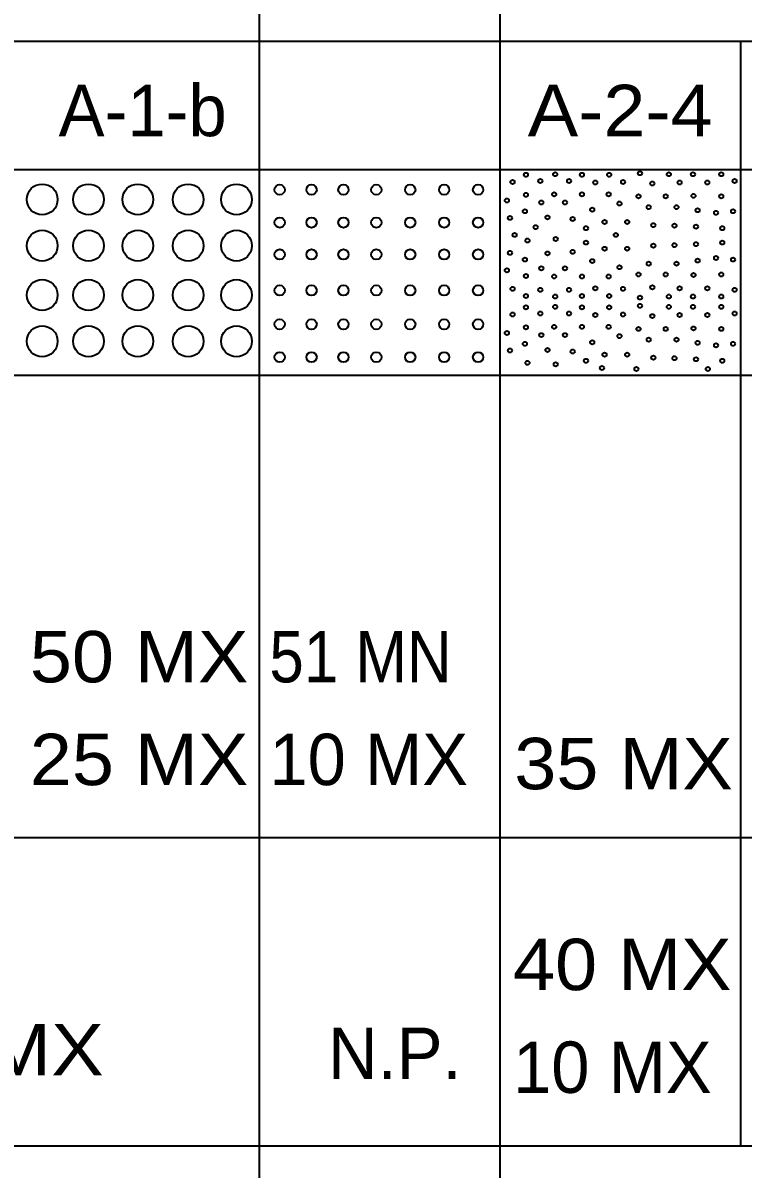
# Model space of a CAD drawing. Extents: x 2137492.6 to 2137529.1, y 2137475.8 to 2137563.
# Drawn here: x 2137494.599 to 2137496, y 2137553.178 to 2137555.408 of the extents above; entities that cross this region are included whole.
import ezdxf
from ezdxf.enums import TextEntityAlignment as Align

# ---------------------------------------------------------------- set-up
doc = ezdxf.new("R2010")
doc.units = 0
doc.header["$LTSCALE"] = 0.04
doc.layers.add('1', color=7, linetype='Continuous', lineweight=35)

msp = doc.modelspace()

# ---------------------------------------------------------------- linework, layer by layer
at = {"layer": '1'}
for p, q in [((2137495.059, 2137552.223), (2137495.059, 2137555.621)), ((2137495.527, 2137552.223), (2137495.527, 2137555.621)), ((2137494.121, 2137555.373), (2137499.271, 2137555.373)), ((2137495.995, 2137553.223), (2137495.995, 2137555.374)), ((2137493.171, 2137555.123), (2137501.871, 2137555.123)), ((2137493.171, 2137554.723), (2137501.871, 2137554.723)), ((2137493.171, 2137553.823), (2137501.871, 2137553.823)), ((2137493.171, 2137553.223), (2137499.271, 2137553.223))]:
    msp.add_line(p, q, dxfattribs=at)
for centre, radius in [((2137495.57706, 2137555.11286), 0.004), ((2137495.63406, 2137555.11386), 0.004), ((2137495.68606, 2137555.11286), 0.004), ((2137495.73906, 2137555.11286), 0.004), ((2137495.79906, 2137555.11586), 0.004), ((2137495.85506, 2137555.11386), 0.004), ((2137495.90206, 2137555.11386), 0.004), ((2137495.95706, 2137555.11386), 0.004), ((2137494.63606, 2137555.06486), 0.03), ((2137494.72606, 2137555.06486), 0.03), ((2137494.82206, 2137555.06486), 0.03), ((2137494.92006, 2137555.06486), 0.03), ((2137495.01406, 2137555.06486), 0.03), ((2137495.09806, 2137555.08386), 0.01), ((2137495.16006, 2137555.08386), 0.01), ((2137495.22206, 2137555.08386), 0.01), ((2137495.28606, 2137555.08386), 0.01), ((2137495.35206, 2137555.08386), 0.01), ((2137495.41806, 2137555.08386), 0.01), ((2137495.48406, 2137555.08386), 0.01), ((2137495.55106, 2137555.09886), 0.004), ((2137495.60506, 2137555.10086), 0.004), ((2137495.66106, 2137555.10086), 0.004), ((2137495.71206, 2137555.09786), 0.004), ((2137495.76606, 2137555.09886), 0.004), ((2137495.82306, 2137555.09586), 0.004), ((2137495.87606, 2137555.09786), 0.004), ((2137495.93006, 2137555.09786), 0.004), ((2137495.98306, 2137555.10086), 0.004), ((2137495.57706, 2137555.07386), 0.004), ((2137495.63206, 2137555.07486), 0.004), ((2137495.68606, 2137555.07486), 0.004), ((2137495.73806, 2137555.07486), 0.004), ((2137495.79606, 2137555.07086), 0.004), ((2137495.84906, 2137555.07086), 0.004), ((2137495.90306, 2137555.07186), 0.004), ((2137495.95706, 2137555.07086), 0.004), ((2137495.54006, 2137555.06286), 0.004), ((2137495.60706, 2137555.05886), 0.004), ((2137495.65306, 2137555.05886), 0.004), ((2137495.70606, 2137555.04486), 0.004), ((2137495.75906, 2137555.05686), 0.004), ((2137495.81606, 2137555.04986), 0.004), ((2137495.87006, 2137555.04986), 0.004), ((2137495.91106, 2137555.04386), 0.004), ((2137495.09806, 2137555.01986), 0.01), ((2137495.16006, 2137555.01986), 0.01), ((2137495.22206, 2137555.01986), 0.01), ((2137495.28606, 2137555.01986), 0.01), ((2137495.35206, 2137555.01986), 0.01), ((2137495.41806, 2137555.01986), 0.01), ((2137495.48406, 2137555.01986), 0.01), ((2137495.54606, 2137555.02886), 0.004), ((2137495.57506, 2137555.04186), 0.004), ((2137495.61906, 2137555.02986), 0.004), ((2137495.66806, 2137555.02686), 0.004), ((2137495.94706, 2137555.03886), 0.004), ((2137495.98006, 2137555.04186), 0.004), ((2137494.63606, 2137554.97486), 0.03), ((2137494.72606, 2137554.97486), 0.03), ((2137494.82206, 2137554.97486), 0.03), ((2137494.92006, 2137554.97486), 0.03), ((2137495.01406, 2137554.97486), 0.03), ((2137495.59606, 2137555.01086), 0.004), ((2137495.69406, 2137555.00886), 0.004), ((2137495.73006, 2137555.02086), 0.004), ((2137495.77406, 2137555.02086), 0.004), ((2137495.82506, 2137555.01486), 0.004), ((2137495.86606, 2137555.01386), 0.004), ((2137495.90806, 2137555.01186), 0.004), ((2137495.95906, 2137555.00886), 0.004), ((2137495.55506, 2137554.99586), 0.004), ((2137495.58006, 2137554.98486), 0.004), ((2137495.63506, 2137554.98786), 0.004), ((2137495.69406, 2137554.98086), 0.004), ((2137495.75206, 2137554.99586), 0.004), ((2137495.90806, 2137554.97786), 0.004), ((2137495.95906, 2137554.98086), 0.004), ((2137495.09806, 2137554.95786), 0.01), ((2137495.16006, 2137554.95786), 0.01), ((2137495.22206, 2137554.95786), 0.01), ((2137495.28606, 2137554.95786), 0.01), ((2137495.35206, 2137554.95786), 0.01), ((2137495.41806, 2137554.95786), 0.01), ((2137495.48406, 2137554.95786), 0.01), ((2137495.54606, 2137554.96086), 0.004), ((2137495.61906, 2137554.95986), 0.004), ((2137495.66806, 2137554.96286), 0.004), ((2137495.73006, 2137554.96886), 0.004), ((2137495.77406, 2137554.96886), 0.004), ((2137495.82506, 2137554.97486), 0.004), ((2137495.86606, 2137554.97586), 0.004), ((2137495.57506, 2137554.94786), 0.004), ((2137495.70606, 2137554.94486), 0.004), ((2137495.75906, 2137554.93286), 0.004), ((2137495.81606, 2137554.93986), 0.004), ((2137495.87006, 2137554.93986), 0.004), ((2137495.91106, 2137554.94586), 0.004), ((2137495.94706, 2137554.95086), 0.004), ((2137495.98006, 2137554.94786), 0.004), ((2137495.54006, 2137554.92686), 0.004), ((2137495.57706, 2137554.91586), 0.004), ((2137495.60706, 2137554.93086), 0.004), ((2137495.63206, 2137554.91486), 0.004), ((2137495.65306, 2137554.93086), 0.004), ((2137495.68606, 2137554.91486), 0.004), ((2137495.73806, 2137554.91486), 0.004), ((2137495.79606, 2137554.91886), 0.004), ((2137495.84906, 2137554.91886), 0.004), ((2137495.90306, 2137554.91786), 0.004), ((2137495.95706, 2137554.91886), 0.004), ((2137494.63606, 2137554.87886), 0.03), ((2137494.72606, 2137554.87886), 0.03), ((2137494.82206, 2137554.87886), 0.03), ((2137494.92006, 2137554.87886), 0.03), ((2137495.01406, 2137554.87886), 0.03), ((2137495.09806, 2137554.88786), 0.01), ((2137495.16006, 2137554.88786), 0.01), ((2137495.22206, 2137554.88786), 0.01), ((2137495.28606, 2137554.88786), 0.01), ((2137495.35206, 2137554.88786), 0.01), ((2137495.41806, 2137554.88786), 0.01), ((2137495.48406, 2137554.88786), 0.01), ((2137495.55106, 2137554.89086), 0.004), ((2137495.60506, 2137554.88886), 0.004), ((2137495.66106, 2137554.88886), 0.004), ((2137495.71206, 2137554.89186), 0.004), ((2137495.76606, 2137554.89086), 0.004), ((2137495.82306, 2137554.89386), 0.004), ((2137495.87606, 2137554.89186), 0.004), ((2137495.93006, 2137554.89186), 0.004), ((2137495.98306, 2137554.88886), 0.004), ((2137495.57706, 2137554.87686), 0.004), ((2137495.63406, 2137554.87586), 0.004), ((2137495.68606, 2137554.87686), 0.004), ((2137495.73906, 2137554.87686), 0.004), ((2137495.79906, 2137554.87386), 0.004), ((2137495.85506, 2137554.87586), 0.004), ((2137495.90206, 2137554.87586), 0.004), ((2137495.95706, 2137554.87586), 0.004), ((2137495.57706, 2137554.85486), 0.004), ((2137495.60506, 2137554.84286), 0.004), ((2137495.63406, 2137554.85586), 0.004), ((2137495.66106, 2137554.84286), 0.004), ((2137495.68606, 2137554.85486), 0.004), ((2137495.73906, 2137554.85486), 0.004), ((2137495.79906, 2137554.85786), 0.004), ((2137495.85506, 2137554.85586), 0.004), ((2137495.90206, 2137554.85586), 0.004), ((2137495.95706, 2137554.85586), 0.004), ((2137495.98306, 2137554.84286), 0.004), ((2137495.09806, 2137554.82186), 0.01), ((2137495.16006, 2137554.82186), 0.01), ((2137495.22206, 2137554.82186), 0.01), ((2137495.28606, 2137554.82186), 0.01), ((2137495.35206, 2137554.82186), 0.01), ((2137495.41806, 2137554.82186), 0.01), ((2137495.48406, 2137554.82186), 0.01), ((2137495.55106, 2137554.84086), 0.004), ((2137495.71206, 2137554.83986), 0.004), ((2137495.76606, 2137554.84086), 0.004), ((2137495.82306, 2137554.83786), 0.004), ((2137495.87606, 2137554.83986), 0.004), ((2137495.93006, 2137554.83986), 0.004), ((2137494.63606, 2137554.78886), 0.03), ((2137494.72606, 2137554.78886), 0.03), ((2137494.82206, 2137554.78886), 0.03), ((2137494.92006, 2137554.78886), 0.03), ((2137495.01406, 2137554.78886), 0.03), ((2137495.54006, 2137554.80486), 0.004), ((2137495.57706, 2137554.81586), 0.004), ((2137495.60706, 2137554.80086), 0.004), ((2137495.63206, 2137554.81686), 0.004), ((2137495.65306, 2137554.80086), 0.004), ((2137495.68606, 2137554.81686), 0.004), ((2137495.73806, 2137554.81686), 0.004), ((2137495.75906, 2137554.79886), 0.004), ((2137495.79606, 2137554.81286), 0.004), ((2137495.84906, 2137554.81286), 0.004), ((2137495.90306, 2137554.81386), 0.004), ((2137495.95706, 2137554.81286), 0.004), ((2137495.57506, 2137554.78386), 0.004), ((2137495.70606, 2137554.78686), 0.004), ((2137495.81606, 2137554.79186), 0.004), ((2137495.87006, 2137554.79186), 0.004), ((2137495.91106, 2137554.78586), 0.004), ((2137495.94706, 2137554.78086), 0.004), ((2137495.98006, 2137554.78386), 0.004), ((2137495.09806, 2137554.75786), 0.01), ((2137495.16006, 2137554.75786), 0.01), ((2137495.22206, 2137554.75786), 0.01), ((2137495.28606, 2137554.75786), 0.01), ((2137495.35206, 2137554.75786), 0.01), ((2137495.41806, 2137554.75786), 0.01), ((2137495.48406, 2137554.75786), 0.01), ((2137495.54606, 2137554.77086), 0.004), ((2137495.61906, 2137554.77186), 0.004), ((2137495.66806, 2137554.76886), 0.004), ((2137495.73006, 2137554.76286), 0.004), ((2137495.77406, 2137554.76286), 0.004), ((2137495.82506, 2137554.75686), 0.004), ((2137495.86606, 2137554.75586), 0.004), ((2137495.90806, 2137554.75386), 0.004), ((2137495.58006, 2137554.74686), 0.004), ((2137495.63506, 2137554.74386), 0.004), ((2137495.69406, 2137554.75086), 0.004), ((2137495.72506, 2137554.73686), 0.004), ((2137495.79206, 2137554.73486), 0.004), ((2137495.93106, 2137554.73486), 0.004), ((2137495.95906, 2137554.75086), 0.004)]:
    msp.add_circle(centre, radius, dxfattribs=at)

# ---------------------------------------------------------------- texts
for s, p in [('A-1-b', (2137494.8315, 2137555.188)), ('N.P.', (2137495.322, 2137553.353))]:
    msp.add_text(s, height=0.1, dxfattribs=at).set_placement(p, align=Align.CENTER)
for s, width, p in [('A-2-4', 1.1, (2137495.7605, 2137555.188)), ('35 MX', 1.1, (2137495.767, 2137553.917)), ('6 MX', 1.15, (2137494.5765, 2137553.36))]:
    msp.add_text(s, height=0.1, dxfattribs=dict(at, width=width)).set_placement(p, align=Align.CENTER)
for s, width, p in [('50 MX', 1.1, (2137494.612, 2137554.125)), ('51 MN', 0.9, (2137495.078, 2137554.125)), ('25 MX', 1.1, (2137494.612, 2137553.925)), ('40 MX', 1.1, (2137495.552, 2137553.526))]:
    msp.add_text(s, height=0.1, dxfattribs=dict(at, width=width)).set_placement(p)
for p in [(2137495.078, 2137553.925), (2137495.552, 2137553.326)]:
    msp.add_text('10 MX', height=0.1, dxfattribs=at).set_placement(p)

doc.saveas('drawing.dxf')
